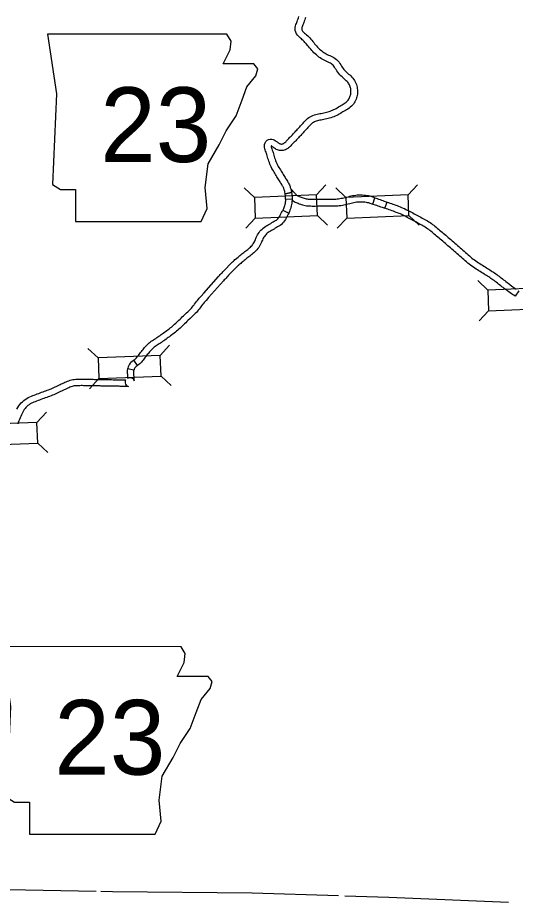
# Model space of a CAD drawing. Extents: x 77230 to 630905, y 790554 to 1662844.
# Drawn here: x 362212 to 381211, y 1374057 to 1407815 of the extents above; entities that cross this region are included whole.
import ezdxf

# ---------------------------------------------------------------- set-up
doc = ezdxf.new("R2010")
doc.units = 0
for name, color, linetype in [('Level 10', 7, 'Continuous'), ('Level 19', 7, 'Continuous'), ('Level 24', 7, 'Continuous'), ('Level 43', 7, 'Continuous')]:
    doc.layers.add(name, color=color, linetype=linetype)

msp = doc.modelspace()

# ---------------------------------------------------------------- linework, layer by layer
at = {"layer": 'Level 10'}
for p, q in [((373211, 1406837), (373213, 1406834)), ((373400, 1407001), (373402, 1406998)), ((373106, 1403789), (373106, 1403788)), ((373291, 1403620), (373291, 1403619)), ((372439, 1400892), (372439, 1400891)), ((376923, 1400276), (376923, 1400276)), ((377033, 1400500), (377035, 1400499)), ((377035, 1400499), (377034, 1400500)), ((369884, 1397940), (369884, 1397940)), ((370070, 1397774), (370070, 1397774)), ((366789, 1394543), (366640, 1394743)), ((366652, 1394362), (366408, 1394415))]:
    msp.add_line(p, q, dxfattribs=at)
for points in [[(373213, 1406834), (373178, 1406874), (373144, 1406910), (373110, 1406944), (373076, 1406976), (373042, 1407006), (373005, 1407035), (372966, 1407068), (372927, 1407106), (372889, 1407150), (372856, 1407200), (372827, 1407257), (372810, 1407321), (372804, 1407382), (372807, 1407444), (372819, 1407502), (372836, 1407553), (372854, 1407596), (372870, 1407636), (372885, 1407675), (372901, 1407719), (372919, 1407766), (372936, 1407811), (372951, 1407858)], [(373204, 1407825), (373188, 1407778), (373171, 1407728), (373152, 1407678), (373135, 1407632), (373119, 1407588), (373102, 1407544), (373086, 1407503), (373071, 1407467), (373061, 1407437), (373056, 1407412), (373055, 1407389), (373057, 1407366), (373062, 1407346), (373073, 1407326), (373089, 1407302), (373109, 1407278), (373134, 1407254), (373166, 1407227), (373203, 1407197), (373243, 1407162), (373284, 1407124), (373323, 1407084), (373362, 1407043), (373400, 1407001)], [(373106, 1403788), (373137, 1403822), (373168, 1403855), (373201, 1403891), (373238, 1403929), (373280, 1403967), (373327, 1404003), (373377, 1404035), (373429, 1404063), (373485, 1404087), (373542, 1404106), (373597, 1404120), (373649, 1404132), (373699, 1404143), (373749, 1404154), (373801, 1404164), (373852, 1404175), (373903, 1404186), (373954, 1404197), (374004, 1404209), (374052, 1404221), (374099, 1404235), (374146, 1404250), (374191, 1404267), (374235, 1404286), (374278, 1404307), (374323, 1404330), (374367, 1404355), (374413, 1404381), (374459, 1404407), (374505, 1404434), (374551, 1404460), (374595, 1404485), (374639, 1404511), (374679, 1404536), (374715, 1404561), (374748, 1404586), (374778, 1404613), (374805, 1404641), (374829, 1404670), (374850, 1404700), (374869, 1404732), (374885, 1404763), (374898, 1404795), (374910, 1404829), (374921, 1404864), (374929, 1404898), (374934, 1404931), (374937, 1404964), (374937, 1405001), (374935, 1405038), (374931, 1405074), (374925, 1405109), (374916, 1405144), (374905, 1405180), (374891, 1405216), (374875, 1405251), (374856, 1405285), (374836, 1405318), (374812, 1405349), (374785, 1405380), (374754, 1405411), (374719, 1405443), (374680, 1405478), (374639, 1405514), (374598, 1405552), (374555, 1405592), (374512, 1405635), (374470, 1405683), (374431, 1405733), (374396, 1405783), (374365, 1405833), (374335, 1405880), (374307, 1405926), (374280, 1405965), (374253, 1405999), (374224, 1406028), (374191, 1406054), (374155, 1406077), (374115, 1406097), (374070, 1406119), (374020, 1406141), (373970, 1406165), (373919, 1406190), (373867, 1406218), (373816, 1406248), (373765, 1406280), (373715, 1406314), (373665, 1406351), (373615, 1406391), (373567, 1406434), (373521, 1406479), (373478, 1406524), (373438, 1406569), (373400, 1406611), (373351, 1406660), (373314, 1406711), (373282, 1406752), (373247, 1406795), (373211, 1406837)], [(373402, 1406998), (373438, 1406955), (373476, 1406910), (373514, 1406862), (373543, 1406822), (373581, 1406783), (373623, 1406737), (373662, 1406695), (373700, 1406654), (373738, 1406617), (373777, 1406582), (373818, 1406549), (373860, 1406518), (373903, 1406489), (373946, 1406461), (373989, 1406436), (374033, 1406413), (374079, 1406390), (374126, 1406368), (374174, 1406346), (374225, 1406322), (374281, 1406294), (374336, 1406258), (374390, 1406216), (374439, 1406167), (374482, 1406114), (374517, 1406062), (374548, 1406012), (374577, 1405966), (374605, 1405921), (374633, 1405880), (374663, 1405842), (374694, 1405806), (374729, 1405771), (374767, 1405735), (374806, 1405700), (374846, 1405664), (374887, 1405629), (374927, 1405591), (374968, 1405550), (375006, 1405507), (375041, 1405461), (375072, 1405412), (375099, 1405363), (375121, 1405313), (375141, 1405263), (375157, 1405213), (375170, 1405161), (375179, 1405109), (375184, 1405057), (375187, 1405007), (375187, 1404955), (375183, 1404902), (375174, 1404849), (375162, 1404799), (375148, 1404751), (375132, 1404705), (375112, 1404657), (375088, 1404610), (375060, 1404564), (375028, 1404519), (374992, 1404475), (374952, 1404433), (374908, 1404394), (374862, 1404359), (374815, 1404326), (374768, 1404297), (374721, 1404269), (374675, 1404243), (374629, 1404217), (374583, 1404191), (374537, 1404164), (374490, 1404137), (374442, 1404110), (374392, 1404084), (374339, 1404058), (374284, 1404035), (374228, 1404014), (374173, 1403996), (374118, 1403980), (374063, 1403966), (374009, 1403953), (373956, 1403942), (373903, 1403931), (373852, 1403920), (373802, 1403909), (373752, 1403898), (373702, 1403888), (373655, 1403877), (373612, 1403866), (373574, 1403854), (373538, 1403838), (373503, 1403819), (373471, 1403798), (373440, 1403775), (373411, 1403749), (373382, 1403719), (373352, 1403687), (373321, 1403653), (373291, 1403620)], [(372425, 1401094), (372409, 1401168), (372407, 1401177), (372405, 1401189), (372401, 1401203), (372397, 1401220), (372391, 1401240), (372383, 1401262), (372376, 1401285), (372367, 1401308), (372356, 1401333), (372343, 1401360), (372328, 1401387), (372312, 1401417), (372293, 1401449), (372273, 1401482), (372251, 1401517), (372230, 1401552), (372207, 1401589), (372183, 1401627), (372159, 1401666), (372135, 1401706), (372110, 1401748), (372084, 1401790), (372057, 1401833), (372030, 1401877), (372002, 1401922), (371974, 1401969), (371945, 1402017), (371917, 1402066), (371889, 1402119), (371863, 1402174), (371840, 1402230), (371820, 1402285), (371802, 1402339), (371784, 1402392), (371768, 1402443), (371752, 1402494), (371737, 1402544), (371723, 1402591), (371711, 1402627), (371694, 1402682), (371679, 1402725), (371665, 1402768), (371651, 1402814), (371640, 1402863), (371634, 1402917), (371638, 1402977), (371656, 1403039), (371690, 1403094), (371735, 1403137), (371791, 1403169), (371852, 1403183), (371910, 1403182), (371961, 1403170), (372005, 1403151), (372042, 1403128), (372070, 1403107), (372095, 1403088), (372117, 1403071), (372142, 1403053), (372166, 1403034), (372184, 1403022), (372202, 1403011), (372218, 1403004), (372234, 1402998), (372250, 1402995), (372268, 1402993), (372288, 1402993), (372306, 1402995), (372325, 1402999), (372344, 1403006), (372361, 1403014), (372378, 1403024), (372397, 1403039), (372417, 1403057), (372445, 1403082), (372463, 1403101), (372489, 1403129), (372515, 1403156), (372540, 1403183), (372566, 1403210), (372592, 1403237), (372619, 1403266), (372647, 1403294), (372675, 1403323), (372701, 1403349), (372727, 1403378), (372755, 1403406), (372784, 1403437), (372812, 1403464), (372836, 1403492), (372864, 1403523), (372893, 1403556), (372923, 1403589), (372953, 1403621), (372984, 1403655), (373014, 1403688), (373045, 1403722), (373076, 1403755), (373106, 1403789)], [(373291, 1403619), (373260, 1403586), (373229, 1403553), (373199, 1403519), (373168, 1403486), (373138, 1403453), (373108, 1403420), (373079, 1403388), (373051, 1403357), (373022, 1403325), (372992, 1403291), (372962, 1403262), (372936, 1403234), (372909, 1403206), (372881, 1403176), (372854, 1403148), (372826, 1403120), (372800, 1403093), (372773, 1403065), (372747, 1403038), (372721, 1403010), (372695, 1402983), (372670, 1402957), (372645, 1402930), (372620, 1402904), (372585, 1402871), (372556, 1402845), (372520, 1402818), (372479, 1402793), (372435, 1402773), (372392, 1402758), (372347, 1402748), (372301, 1402743), (372256, 1402743), (372212, 1402748), (372167, 1402757), (372125, 1402772), (372086, 1402789), (372051, 1402810), (372018, 1402833), (371992, 1402853), (371968, 1402870), (371942, 1402890), (371919, 1402908), (371901, 1402921), (371889, 1402929), (371885, 1402930), (371885, 1402923), (371887, 1402904), (371893, 1402878), (371903, 1402844), (371917, 1402804), (371931, 1402760), (371950, 1402703), (371962, 1402665), (371976, 1402617), (371991, 1402568), (372007, 1402517), (372022, 1402468), (372039, 1402419), (372056, 1402368), (372073, 1402321), (372092, 1402275), (372113, 1402231), (372136, 1402187), (372162, 1402142), (372188, 1402097), (372215, 1402053), (372242, 1402008), (372270, 1401964), (372297, 1401921), (372323, 1401878), (372348, 1401836), (372373, 1401796), (372396, 1401758), (372420, 1401720), (372442, 1401684), (372465, 1401647), (372486, 1401612), (372507, 1401577), (372528, 1401542), (372548, 1401507), (372566, 1401471), (372583, 1401437), (372597, 1401404), (372610, 1401372), (372621, 1401341), (372629, 1401314), (372637, 1401289), (372643, 1401266), (372648, 1401246), (372652, 1401230), (372654, 1401221), (372669, 1401146), (372425, 1401094)], [(375773, 1400703), (375849, 1400941), (375670, 1400998), (375610, 1401012), (375549, 1401023), (375486, 1401031), (375428, 1401035), (375366, 1401041), (375301, 1401041), (375240, 1401040), (375178, 1401037), (375116, 1401030), (375056, 1401022), (374994, 1401012), (374935, 1400998), (374882, 1400985), (374827, 1400971), (374773, 1400957), (374720, 1400944), (374667, 1400931), (374615, 1400919), (374563, 1400909), (374511, 1400901), (374458, 1400894), (374405, 1400888), (374353, 1400883), (374301, 1400881), (374249, 1400879), (374195, 1400879), (374141, 1400879), (374088, 1400879), (374034, 1400879), (373982, 1400879), (373929, 1400880), (373877, 1400880), (373825, 1400880), (373772, 1400879), (373720, 1400879), (373669, 1400879), (373616, 1400879), (373564, 1400878), (373512, 1400878), (373462, 1400878), (373412, 1400879), (373363, 1400880), (373319, 1400883), (373278, 1400887), (373240, 1400893), (373202, 1400903), (373162, 1400914), (373121, 1400927), (373083, 1400939), (373046, 1400952), (373009, 1400966), (372974, 1400979), (372943, 1400992), (372916, 1401004), (372893, 1401016), (372874, 1401030), (372856, 1401045), (372839, 1401062), (372821, 1401082), (372805, 1401102), (372742, 1401174), (372695, 1401229), (372637, 1401287), (372669, 1401146), (372687, 1401007), (372688, 1400860)], [(372425, 1401094), (372669, 1401146), (372677, 1401094), (372681, 1401063), (372685, 1401025), (372688, 1400983), (372689, 1400936), (372689, 1400886), (372689, 1400879), (372439, 1400892)], [(372439, 1400891), (372439, 1400892), (372439, 1400931), (372438, 1400970), (372436, 1401005), (372433, 1401034), (372430, 1401060), (372425, 1401094)], [(375849, 1400941), (375886, 1400929), (375939, 1400911), (375991, 1400892), (376045, 1400874), (376098, 1400855), (376153, 1400836), (376207, 1400816), (376318, 1400777)], [(372439, 1400892), (372438, 1400853), (372434, 1400811), (372429, 1400769), (372422, 1400726), (372413, 1400683), (372403, 1400641), (372390, 1400599), (372375, 1400558), (372357, 1400515), (372335, 1400469)], [(372689, 1400879), (372682, 1400785), (372676, 1400733), (372668, 1400682), (372657, 1400629), (372644, 1400575), (372628, 1400520), (372608, 1400466), (372585, 1400413), (372560, 1400361)], [(372688, 1400860), (372723, 1400830), (372762, 1400803), (372803, 1400781), (372844, 1400762), (372883, 1400746), (372922, 1400732), (372961, 1400717), (373003, 1400703), (373046, 1400689), (373090, 1400675), (373137, 1400661), (373189, 1400649), (373244, 1400639), (373300, 1400633), (373354, 1400631), (373406, 1400629), (373458, 1400628), (373512, 1400628), (373565, 1400628), (373617, 1400629), (373670, 1400629), (373722, 1400629), (373774, 1400629), (373826, 1400630), (373877, 1400630), (373928, 1400630), (373981, 1400629), (374033, 1400629), (374087, 1400629), (374141, 1400629), (374196, 1400629), (374253, 1400629), (374311, 1400631), (374370, 1400634), (374429, 1400639), (374488, 1400646), (374547, 1400654), (374607, 1400663), (374666, 1400674), (374724, 1400688), (374780, 1400701), (374835, 1400715), (374889, 1400729), (374941, 1400742), (374995, 1400755), (375044, 1400767), (375093, 1400775), (375145, 1400782), (375197, 1400787), (375249, 1400790), (375303, 1400791), (375353, 1400791), (375408, 1400786), (375461, 1400782), (375511, 1400776), (375559, 1400767), (375607, 1400756), (375655, 1400742), (375773, 1400703)], [(375773, 1400703), (375857, 1400674), (375909, 1400656), (375963, 1400638), (376016, 1400619), (376069, 1400600), (376123, 1400581), (376235, 1400541)], [(376924, 1400275), (376872, 1400300), (376821, 1400324), (376770, 1400346), (376718, 1400367), (376666, 1400387), (376612, 1400407), (376558, 1400427), (376503, 1400446), (376449, 1400466), (376395, 1400485), (376341, 1400504), (376287, 1400523), (376235, 1400541), (376318, 1400777)], [(376318, 1400777), (376370, 1400759), (376424, 1400740), (376479, 1400721), (376533, 1400701), (376588, 1400681), (376643, 1400662), (376697, 1400642), (376753, 1400621), (376810, 1400600), (376867, 1400577), (376923, 1400552), (376979, 1400527), (377033, 1400500)], [(369884, 1397940), (369915, 1397975), (369948, 1398012), (369981, 1398048), (370015, 1398084), (370047, 1398119), (370081, 1398157), (370391, 1398472), (370417, 1398502), (370447, 1398529), (370473, 1398552), (370507, 1398581), (370563, 1398619), (370584, 1398644), (370627, 1398680), (370663, 1398710), (370699, 1398739), (370735, 1398769), (370772, 1398799), (370810, 1398829), (370848, 1398859), (370886, 1398888), (370923, 1398917), (370961, 1398945), (370997, 1398973), (371032, 1399002), (371066, 1399032), (371099, 1399062), (371130, 1399092), (371158, 1399123), (371183, 1399154), (371207, 1399188), (371229, 1399225), (371251, 1399263), (371270, 1399303), (371288, 1399342), (371305, 1399383), (371323, 1399426), (371342, 1399473), (371366, 1399523), (371395, 1399572), (371427, 1399618), (371461, 1399663), (371499, 1399706), (371541, 1399747), (371587, 1399787), (371636, 1399823), (371686, 1399855), (371734, 1399884), (371781, 1399912), (371827, 1399940), (371874, 1399967), (371920, 1399994), (371966, 1400021), (372010, 1400046), (372051, 1400071), (372087, 1400094), (372118, 1400118), (372145, 1400143), (372170, 1400171), (372193, 1400203), (372216, 1400240), (372239, 1400284), (372264, 1400331), (372289, 1400378), (372313, 1400425), (372335, 1400469), (372560, 1400361)], [(372560, 1400361), (372536, 1400312), (372511, 1400263), (372485, 1400214), (372460, 1400166), (372433, 1400117), (372402, 1400065), (372366, 1400015), (372324, 1399968), (372279, 1399926), (372231, 1399890), (372184, 1399859), (372137, 1399831), (372092, 1399804), (372046, 1399778), (372000, 1399751), (371954, 1399724), (371908, 1399697), (371862, 1399670), (371818, 1399643), (371778, 1399618), (371743, 1399591), (371711, 1399564), (371681, 1399534), (371654, 1399503), (371629, 1399471), (371607, 1399438), (371587, 1399405), (371570, 1399370), (371553, 1399330), (371536, 1399288), (371517, 1399243), (371496, 1399196), (371472, 1399148), (371446, 1399100), (371416, 1399051), (371383, 1399004), (371347, 1398959), (371309, 1398918), (371271, 1398881), (371233, 1398845), (371193, 1398811), (371153, 1398778), (371113, 1398747), (371075, 1398718), (371039, 1398690), (371002, 1398662), (370965, 1398633), (370928, 1398604), (370892, 1398575), (370857, 1398545), (370822, 1398517), (370788, 1398488), (370761, 1398467), (370731, 1398431), (370658, 1398382), (370637, 1398364), (370613, 1398342), (370594, 1398325), (370574, 1398302), (370265, 1397987), (370233, 1397951), (370198, 1397914), (370165, 1397878), (370132, 1397843), (370101, 1397808), (370070, 1397774)], [(381211, 1397184), (381154, 1397221), (381107, 1397252), (381061, 1397282), (381013, 1397314), (380966, 1397347), (380921, 1397380), (380859, 1397427), (380832, 1397448), (380788, 1397482), (380744, 1397516), (380700, 1397550), (380656, 1397584), (380612, 1397618), (380568, 1397651), (380525, 1397684), (380482, 1397717), (380439, 1397750), (380398, 1397781), (380358, 1397811), (380318, 1397840), (380278, 1397868), (380238, 1397895), (380197, 1397921), (380155, 1397947), (380111, 1397975), (380065, 1398003), (380019, 1398032), (379972, 1398062), (379924, 1398092), (379874, 1398123), (379823, 1398155), (379771, 1398188), (379719, 1398221), (379666, 1398255), (379611, 1398291), (379555, 1398328), (379500, 1398368), (379446, 1398409), (379393, 1398452), (379342, 1398495), (379292, 1398538), (379243, 1398581), (379193, 1398625), (379142, 1398670), (379092, 1398715), (379042, 1398759), (378991, 1398804), (378939, 1398849), (378888, 1398894), (378837, 1398938), (378786, 1398982), (378736, 1399026), (378687, 1399070), (378638, 1399113), (378588, 1399155), (378539, 1399197), (378490, 1399239), (378442, 1399281), (378394, 1399322), (378346, 1399363), (378298, 1399403), (378251, 1399443), (378205, 1399482), (378160, 1399521), (378116, 1399558), (378073, 1399594), (378032, 1399629), (377990, 1399662), (377948, 1399694), (377905, 1399726), (377862, 1399757), (377818, 1399787), (377775, 1399815), (377730, 1399843), (377683, 1399870), (377636, 1399896), (377586, 1399923), (377536, 1399951), (377485, 1399979), (377435, 1400006), (377384, 1400033), (377333, 1400060), (377282, 1400087), (377230, 1400115), (377179, 1400142), (377128, 1400169), (377077, 1400196), (377025, 1400223), (376924, 1400275)], [(377035, 1400499), (377193, 1400417), (377245, 1400390), (377296, 1400363), (377348, 1400335), (377399, 1400308), (377450, 1400281), (377502, 1400254), (377553, 1400226), (377605, 1400198), (377656, 1400170), (377706, 1400143), (377757, 1400115), (377808, 1400087), (377858, 1400057), (377909, 1400026), (377958, 1399994), (378006, 1399961), (378052, 1399928), (378098, 1399894), (378143, 1399859), (378189, 1399823), (378233, 1399786), (378278, 1399749), (378322, 1399711), (378367, 1399673), (378413, 1399634), (378460, 1399594), (378508, 1399554), (378556, 1399512), (378605, 1399471), (378653, 1399429), (378702, 1399387), (378752, 1399344), (378801, 1399301), (378851, 1399258), (378901, 1399214), (378951, 1399171), (379001, 1399127), (379052, 1399082), (379103, 1399037), (379155, 1398993), (379207, 1398947), (379259, 1398901), (379309, 1398856), (379358, 1398812), (379407, 1398769), (379456, 1398727), (379504, 1398685), (379552, 1398644), (379600, 1398606), (379649, 1398569), (379698, 1398533), (379749, 1398499), (379801, 1398465), (379853, 1398432), (379905, 1398398), (379956, 1398366), (380006, 1398335), (380056, 1398304), (380105, 1398274), (380152, 1398244), (380198, 1398215), (380242, 1398187), (380287, 1398160), (380332, 1398132), (380376, 1398103), (380419, 1398074), (380462, 1398044), (380505, 1398013), (380548, 1397981), (380591, 1397949), (380633, 1397916), (380676, 1397883), (380720, 1397850), (380764, 1397816), (380809, 1397782), (380853, 1397748), (380897, 1397714), (380941, 1397680), (380985, 1397646), (381010, 1397626), (381071, 1397581), (381113, 1397549), (381155, 1397520), (381198, 1397491), (381244, 1397461)], [(366640, 1394743), (366679, 1394773), (366706, 1394795), (366732, 1394819), (366754, 1394840), (366777, 1394868), (366803, 1394899), (366826, 1394930), (366851, 1394965), (366878, 1395003), (366907, 1395041), (366934, 1395078), (366966, 1395120), (366998, 1395156), (367026, 1395189), (367055, 1395225), (367087, 1395261), (367119, 1395297), (367154, 1395334), (367192, 1395369), (367231, 1395403), (367272, 1395436), (367314, 1395466), (367356, 1395495), (367398, 1395523), (367440, 1395551), (367482, 1395578), (367523, 1395605), (367564, 1395633), (367604, 1395660), (367646, 1395689), (367687, 1395719), (367729, 1395749), (367770, 1395778), (367813, 1395812), (367859, 1395844), (367902, 1395876), (367946, 1395908), (367990, 1395941), (368034, 1395975), (368078, 1396009), (368120, 1396043), (368163, 1396079), (368205, 1396115), (368246, 1396152), (368286, 1396190), (368328, 1396230), (368369, 1396270), (368411, 1396311), (368451, 1396350), (368493, 1396393), (368537, 1396435), (368621, 1396514), (368663, 1396553), (368703, 1396591), (368821, 1396704), (368851, 1396733), (368878, 1396770), (368913, 1396817), (368945, 1396851), (368968, 1396888), (369001, 1396936), (369036, 1396980), (369071, 1397025), (369111, 1397069), (369146, 1397106), (369180, 1397146), (369216, 1397186), (369314, 1397303), (369884, 1397940)], [(370070, 1397774), (369503, 1397139), (369404, 1397022), (369369, 1396983), (369333, 1396940), (369295, 1396899), (369263, 1396865), (369233, 1396825), (369202, 1396787), (369176, 1396749), (369143, 1396698), (369106, 1396657), (369079, 1396621), (369040, 1396568), (368994, 1396524), (368876, 1396411), (368835, 1396372), (368793, 1396332), (368708, 1396253), (368668, 1396215), (368629, 1396174), (368586, 1396132), (368544, 1396091), (368502, 1396050), (368459, 1396009), (368415, 1395967), (368369, 1395927), (368324, 1395888), (368279, 1395851), (368233, 1395813), (368186, 1395777), (368141, 1395742), (368095, 1395708), (368051, 1395675), (368005, 1395641), (367961, 1395611), (367921, 1395579), (367875, 1395546), (367832, 1395515), (367789, 1395485), (367746, 1395455), (367704, 1395426), (367661, 1395397), (367619, 1395369), (367577, 1395342), (367537, 1395315), (367497, 1395289), (367459, 1395262), (367424, 1395237), (367391, 1395210), (367359, 1395183), (367330, 1395156), (367302, 1395127), (367274, 1395095), (367246, 1395063), (367217, 1395029), (367187, 1394993), (367160, 1394962), (367134, 1394928), (367106, 1394891), (367080, 1394856), (367055, 1394820), (367028, 1394782), (366999, 1394743), (366970, 1394709), (366939, 1394670), (366903, 1394636), (366870, 1394606), (366834, 1394576), (366789, 1394543)], [(381349, 1397392), (381211, 1397184)], [(366640, 1394743), (366618, 1394727), (366580, 1394697), (366534, 1394656), (366511, 1394632), (366478, 1394589), (366451, 1394543), (366428, 1394493), (366413, 1394442), (366408, 1394415)], [(366789, 1394543), (366769, 1394528), (366741, 1394506), (366708, 1394476), (366700, 1394468), (366685, 1394449), (366673, 1394428), (366664, 1394407), (366656, 1394381), (366652, 1394362)], [(366408, 1394415), (366397, 1394345), (366394, 1394296), (366395, 1394251), (366398, 1394210), (366400, 1394172), (366403, 1394136), (366406, 1394100), (366409, 1394063), (366441, 1394075), (366480, 1394083), (366521, 1394081), (366558, 1394069), (366578, 1394059), (366604, 1394040), (366641, 1393997), (366659, 1393952)], [(366659, 1393952), (366661, 1393986), (366660, 1394020), (366660, 1394050), (366658, 1394086), (366655, 1394120), (366652, 1394154), (366650, 1394189), (366647, 1394225), (366645, 1394261), (366645, 1394293), (366646, 1394323), (366652, 1394362)], [(362183, 1392879), (362217, 1392942), (362256, 1393002), (362298, 1393059), (362344, 1393112), (362393, 1393162), (362445, 1393208), (362500, 1393250), (362557, 1393288), (362614, 1393320), (362675, 1393352), (362736, 1393375), (362791, 1393396), (362845, 1393416), (362900, 1393437), (362957, 1393458), (363013, 1393478), (363069, 1393498), (363124, 1393519), (363180, 1393539), (363236, 1393560), (363290, 1393579), (363343, 1393599), (363394, 1393618), (363446, 1393639), (363495, 1393657), (363541, 1393677), (363589, 1393699), (363638, 1393722), (363686, 1393745), (363732, 1393768), (363782, 1393794), (363833, 1393816), (363878, 1393837), (363925, 1393858), (363971, 1393880), (364017, 1393901), (364063, 1393922), (364111, 1393944), (364161, 1393963), (364212, 1393981), (364265, 1393995), (364319, 1394007), (364373, 1394014), (364427, 1394020), (364483, 1394023), (364535, 1394021), (364581, 1394022), (364631, 1394023), (364681, 1394023), (364730, 1394022), (364774, 1394020), (364820, 1394020), (364857, 1394019)], [(364858, 1394019), (364867, 1394019), (364911, 1394018), (364956, 1394018), (365003, 1394017), (365054, 1394016), (365095, 1394015), (365141, 1394014), (365186, 1394013), (365232, 1394013), (365276, 1394011), (365319, 1394011), (365361, 1394010), (365405, 1394009), (365445, 1394008), (365491, 1394006), (365533, 1394005), (365574, 1394004), (365614, 1394004), (365655, 1394003), (365694, 1394003), (365734, 1394002), (365773, 1394002), (365798, 1394002), (365855, 1394001), (365895, 1394000), (365932, 1393999), (365970, 1394000), (366010, 1394000), (366049, 1393999), (366089, 1393998), (366128, 1393996), (366168, 1393995), (366206, 1393994), (366244, 1393992), (366282, 1393991), (366318, 1393990), (366334, 1393989), (366319, 1393950), (366314, 1393916), (366316, 1393877), (366329, 1393836), (366356, 1393793), (366391, 1393763), (366416, 1393749), (366444, 1393739)], [(366415, 1393737), (366381, 1393737), (366326, 1393739), (366309, 1393740), (366272, 1393741), (366235, 1393742), (366197, 1393744), (366159, 1393745), (366120, 1393746), (366081, 1393748), (366043, 1393749), (366006, 1393750), (365970, 1393750), (365931, 1393749), (365890, 1393750), (365850, 1393751), (365796, 1393752), (365773, 1393752), (365732, 1393752), (365691, 1393753), (365651, 1393753), (365610, 1393754), (365569, 1393754), (365527, 1393755), (365483, 1393756), (365436, 1393758), (365398, 1393759), (365357, 1393760), (365315, 1393761), (365270, 1393762), (365226, 1393763), (365181, 1393764), (365136, 1393764), (365090, 1393765), (365049, 1393766), (364999, 1393767), (364954, 1393768), (364907, 1393768), (364860, 1393769), (364816, 1393770), (364771, 1393770), (364723, 1393772), (364678, 1393773), (364632, 1393773), (364586, 1393772), (364534, 1393771), (364487, 1393772), (364445, 1393770), (364402, 1393766), (364362, 1393760), (364324, 1393752), (364286, 1393742), (364247, 1393728), (364207, 1393713), (364165, 1393694), (364121, 1393674), (364076, 1393653), (364030, 1393632), (363984, 1393610), (363935, 1393588), (363889, 1393568), (363845, 1393545), (363796, 1393521), (363746, 1393497), (363695, 1393473), (363643, 1393449), (363588, 1393425), (363535, 1393405), (363484, 1393385), (363430, 1393365), (363376, 1393345), (363321, 1393325), (363267, 1393305), (363211, 1393284), (363155, 1393264), (363098, 1393243), (363043, 1393223), (362989, 1393204), (362934, 1393182), (362879, 1393162), (362824, 1393141), (362777, 1393123), (362733, 1393100), (362687, 1393074), (362645, 1393046), (362604, 1393015), (362565, 1392981), (362528, 1392943), (362494, 1392902), (362461, 1392859), (362433, 1392815), (362407, 1392767), (362383, 1392715), (362359, 1392660), (362335, 1392602), (362310, 1392544), (362286, 1392487), (362261, 1392429), (362236, 1392372), (362212, 1392314)]]:
    msp.add_lwpolyline(points, dxfattribs=at)
at = {"layer": 'Level 19'}
for p, q in [((371249, 1400958), (370861, 1401317)), ((373623, 1401052), (373981, 1401440)), ((374742, 1400958), (374354, 1401317)), ((377116, 1401052), (377475, 1401440)), ((373654, 1400261), (374042, 1399902)), ((377148, 1400261), (377535, 1399902)), ((371280, 1400167), (370922, 1399779)), ((374774, 1400167), (374415, 1399779)), ((380162, 1397423), (379774, 1397782)), ((380193, 1396632), (379835, 1396244)), ((365282, 1394833), (364894, 1395192)), ((367656, 1394927), (368014, 1395315)), ((365313, 1394042), (364955, 1393654)), ((367687, 1394136), (368075, 1393777)), ((362949, 1392371), (363308, 1392759)), ((362981, 1391580), (363369, 1391221))]:
    msp.add_line(p, q, dxfattribs=at)
for points in [[(371280, 1400167), (373654, 1400261), (373623, 1401052), (371249, 1400958)], [(374774, 1400167), (377148, 1400261), (377116, 1401052), (374742, 1400958)], [(380193, 1396632), (382567, 1396726), (382536, 1397517), (380162, 1397423)], [(365313, 1394042), (367687, 1394136), (367656, 1394927), (365282, 1394833)], [(360607, 1391486), (362981, 1391580), (362949, 1392371), (360575, 1392277)]]:
    msp.add_lwpolyline(points, close=True, dxfattribs=at)
at = {"layer": 'Level 24'}
for points in [[(363353, 1407192), (363696, 1404908), (363543, 1401444), (363848, 1401254), (364419, 1401254), (364419, 1400036), (369215, 1400036), (369444, 1400530), (369367, 1401330), (369482, 1402243), (369900, 1402967), (370167, 1403499), (370547, 1404070), (370776, 1404679), (370966, 1405174), (371309, 1405593), (371385, 1405859), (371233, 1406050), (370053, 1406050), (370319, 1406583), (370357, 1406925), (370199, 1407188)], [(361601, 1383814), (361943, 1381530), (361791, 1378066), (362096, 1377876), (362667, 1377876), (362667, 1376658), (367463, 1376658), (367691, 1377153), (367615, 1377952), (367729, 1378866), (368148, 1379589), (368414, 1380122), (368795, 1380693), (369023, 1381302), (369214, 1381797), (369556, 1382215), (369633, 1382482), (369480, 1382672), (368300, 1382672), (368567, 1383205), (368605, 1383548), (368447, 1383811)]]:
    msp.add_lwpolyline(points, close=True, dxfattribs=at)
at = {"layer": 'Level 43'}
for points in [[(356160, 1374745), (360479, 1374576), (365206, 1374486)], [(365384, 1374483), (365833, 1374475), (371160, 1374423), (374456, 1374315)], [(374698, 1374307), (376384, 1374251), (380953, 1374057)]]:
    msp.add_lwpolyline(points, dxfattribs=at)

# ---------------------------------------------------------------- texts
at = {"layer": 'Level 24'}
for p in [(365362, 1402307), (363609, 1378929)]:
    msp.add_text('23', height=2851.2, dxfattribs=at).set_placement(p)

doc.saveas('drawing.dxf')
